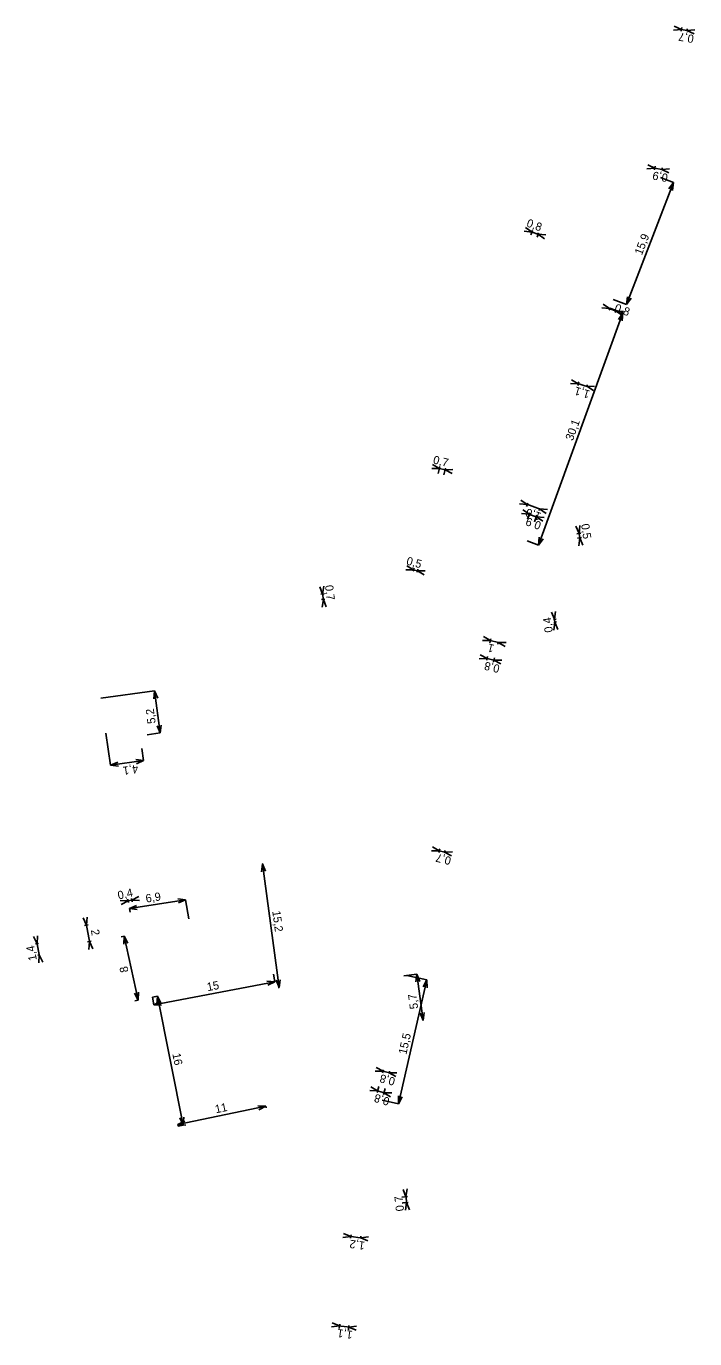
# Model space of a CAD drawing. Extents: x -732085 to -731961, y -1048713 to -1047966.
# Drawn here: x -732085.2 to -732003.6, y -1048336.6 to -1048176.6 of the extents above; entities that cross this region are included whole.
import ezdxf

# ---------------------------------------------------------------- set-up
doc = ezdxf.new("R2010")
doc.units = 0
doc.layers.add('Kota_NN', color=7, linetype='Continuous')
doc.layers.add('Kota_VN', color=7, linetype='Continuous')

msp = doc.modelspace()

# ---------------------------------------------------------------- linework, layer by layer
at = {"layer": 'Kota_NN'}
for p, q in [((-732011.96, -1048210.54), (-732006.25, -1048195.66)), ((-732007.84, -1048195.05), (-732006.25, -1048195.66)), ((-732006.25, -1048195.66), (-732006.81, -1048196.44)), ((-732006.25, -1048195.66), (-732006.35, -1048196.62)), ((-732023.5, -1048201.7), (-732024.46, -1048201.61)), ((-732023.5, -1048201.7), (-732024.29, -1048201.14)), ((-732023.69, -1048201.63), (-732022.58, -1048202.03)), ((-732023.63, -1048202.04), (-732023.44, -1048201.51)), ((-732022.89, -1048202.31), (-732022.7, -1048201.78)), ((-732022.77, -1048201.96), (-732021.81, -1048202.05)), ((-732022.77, -1048201.96), (-732021.98, -1048202.51)), ((-732013.59, -1048209.91), (-732011.96, -1048210.54)), ((-732011.96, -1048210.54), (-732011.86, -1048209.58)), ((-732011.96, -1048210.54), (-732011.4, -1048209.76)), ((-732022.7, -1048239.87), (-732012.41, -1048211.56)), ((-732014.03, -1048211.04), (-732014.98, -1048210.96)), ((-732014.03, -1048211.04), (-732014.82, -1048210.5)), ((-732014.21, -1048210.98), (-732013.11, -1048211.37)), ((-732014.01, -1048210.99), (-732014.09, -1048211.23)), ((-732014, -1048210.98), (-732012.41, -1048211.56)), ((-732013.28, -1048211.25), (-732013.37, -1048211.49)), ((-732013.3, -1048211.31), (-732012.34, -1048211.39)), ((-732013.3, -1048211.31), (-732012.51, -1048211.85)), ((-732012.41, -1048211.56), (-732012.96, -1048212.35)), ((-732012.41, -1048211.56), (-732012.5, -1048212.52)), ((-732034.78, -1048230.52), (-732035.74, -1048230.54)), ((-732034.78, -1048230.52), (-732035.63, -1048230.05)), ((-732034.98, -1048230.47), (-732033.91, -1048230.73)), ((-732034.93, -1048231.12), (-732034.74, -1048230.32)), ((-732034.25, -1048231.29), (-732034.06, -1048230.49)), ((-732034.1, -1048230.68), (-732033.14, -1048230.66)), ((-732034.1, -1048230.68), (-732033.26, -1048231.14)), ((-732023.82, -1048236.1), (-732024.61, -1048235.55)), ((-732024.04, -1048236.71), (-732023.76, -1048235.92)), ((-732023.82, -1048236.1), (-732024.78, -1048236.02)), ((-732022.78, -1048236.48), (-732024.01, -1048236.04)), ((-732023.19, -1048237.02), (-732022.9, -1048236.23)), ((-732022.97, -1048236.41), (-732022.01, -1048236.5)), ((-732022.97, -1048236.41), (-732022.18, -1048236.96)), ((-732017.76, -1048238.44), (-732018.14, -1048237.56)), ((-732017.76, -1048238.44), (-732017.65, -1048237.48)), ((-732022.7, -1048239.87), (-732022.61, -1048238.91)), ((-732022.7, -1048239.87), (-732022.15, -1048239.08)), ((-732018.03, -1048238.48), (-732017.56, -1048238.41)), ((-732017.95, -1048239.01), (-732017.48, -1048238.94)), ((-732017.79, -1048238.24), (-732017.64, -1048239.17)), ((-732017.67, -1048238.97), (-732017.78, -1048239.93)), ((-732017.67, -1048238.97), (-732017.29, -1048239.85)), ((-732024.09, -1048239.36), (-732022.7, -1048239.87)), ((-732037.94, -1048242.88), (-732038.78, -1048242.4)), ((-732037.94, -1048242.88), (-732038.9, -1048242.88)), ((-732038.14, -1048242.83), (-732037.29, -1048243.05)), ((-732037.98, -1048243.02), (-732037.89, -1048242.69)), ((-732037.52, -1048243.14), (-732037.43, -1048242.81)), ((-732037.48, -1048243), (-732036.52, -1048243)), ((-732037.48, -1048243), (-732036.65, -1048243.48)), ((-732049.04, -1048245.83), (-732049.4, -1048244.94)), ((-732049.04, -1048245.83), (-732048.9, -1048244.88)), ((-732049.24, -1048245.86), (-732048.84, -1048245.81)), ((-732049.16, -1048246.51), (-732048.76, -1048246.46)), ((-732048.95, -1048246.48), (-732049.09, -1048247.44)), ((-732049.06, -1048245.64), (-732048.93, -1048246.68)), ((-732048.95, -1048246.48), (-732048.59, -1048247.37)), ((-732020.76, -1048248.9), (-732021.14, -1048248.02)), ((-732020.69, -1048249.46), (-732020.79, -1048248.71)), ((-732020.76, -1048248.9), (-732020.64, -1048247.95)), ((-732020.88, -1048248.92), (-732020.57, -1048248.88)), ((-732020.83, -1048249.28), (-732020.52, -1048249.23)), ((-732020.71, -1048249.26), (-732020.83, -1048250.21)), ((-732020.71, -1048249.26), (-732020.34, -1048250.15)), ((-732028.98, -1048253.7), (-732029.82, -1048253.24)), ((-732028.91, -1048253.43), (-732029.02, -1048253.89)), ((-732028.98, -1048253.7), (-732029.94, -1048253.72)), ((-732027.96, -1048253.94), (-732029.17, -1048253.65)), ((-732028.09, -1048253.62), (-732028.2, -1048254.09)), ((-732028.15, -1048253.89), (-732027.19, -1048253.87)), ((-732028.15, -1048253.89), (-732027.31, -1048254.35)), ((-732076.09, -1048258.53), (-732069.53, -1048257.64)), ((-732069.53, -1048257.64), (-732069.65, -1048258.6)), ((-732068.84, -1048262.75), (-732069.53, -1048257.64)), ((-732069.53, -1048257.64), (-732069.16, -1048258.53)), ((-732075.47, -1048262.79), (-732074.92, -1048266.7)), ((-732070.45, -1048262.97), (-732068.84, -1048262.75)), ((-732068.84, -1048262.75), (-732069.21, -1048261.87)), ((-732068.84, -1048262.75), (-732068.72, -1048261.8)), ((-732071.08, -1048264.67), (-732070.88, -1048266.13)), ((-732070.88, -1048266.13), (-732074.92, -1048266.7)), ((-732074.92, -1048266.7), (-732074.03, -1048266.32)), ((-732070.88, -1048266.13), (-732071.83, -1048266.01)), ((-732070.88, -1048266.13), (-732071.76, -1048266.5)), ((-732074.92, -1048266.7), (-732073.96, -1048266.82)), ((-732072.77, -1048283.21), (-732073.73, -1048283.17)), ((-732072.77, -1048283.21), (-732073.62, -1048283.65)), ((-732072.96, -1048283.26), (-732072.14, -1048283.08)), ((-732072.72, -1048283.44), (-732072.81, -1048283.02)), ((-732072.6, -1048284.17), (-732065.76, -1048283.08)), ((-732072.6, -1048284.17), (-732071.73, -1048283.78)), ((-732072.28, -1048283.34), (-732072.37, -1048282.92)), ((-732072.33, -1048283.12), (-732071.48, -1048282.68)), ((-732072.33, -1048283.12), (-732071.37, -1048283.16)), ((-732065.76, -1048283.08), (-732066.72, -1048282.98)), ((-732065.76, -1048283.08), (-732066.64, -1048283.47)), ((-732065.38, -1048285.42), (-732065.76, -1048283.08)), ((-732077.83, -1048286.17), (-732078.24, -1048285.3)), ((-732077.83, -1048286.17), (-732077.75, -1048285.21)), ((-732072.53, -1048284.61), (-732072.6, -1048284.17)), ((-732072.6, -1048284.17), (-732071.65, -1048284.27)), ((-732078.09, -1048286.22), (-732077.64, -1048286.14)), ((-732077.87, -1048285.97), (-732077.44, -1048288.38)), ((-732077.73, -1048288.23), (-732077.28, -1048288.15)), ((-732077.47, -1048288.18), (-732077.55, -1048289.14)), ((-732077.47, -1048288.18), (-732077.07, -1048289.05)), ((-732073.63, -1048287.62), (-732073.23, -1048287.53)), ((-732073.23, -1048287.53), (-732073.28, -1048288.49)), ((-732071.55, -1048295.32), (-732073.23, -1048287.53)), ((-732073.23, -1048287.53), (-732072.79, -1048288.39)), ((-732069.64, -1048295.88), (-732054.87, -1048293.08)), ((-732054.87, -1048293.08), (-732055.83, -1048293.01)), ((-732054.87, -1048293.08), (-732055.74, -1048293.5)), ((-732055.05, -1048292.16), (-732054.87, -1048293.08)), ((-732039.77, -1048307.95), (-732036.34, -1048292.86)), ((-732038.77, -1048292.31), (-732036.34, -1048292.86)), ((-732036.34, -1048292.86), (-732036.79, -1048293.71)), ((-732036.34, -1048292.86), (-732036.31, -1048293.82)), ((-732071.55, -1048295.32), (-732071.99, -1048294.46)), ((-732071.55, -1048295.32), (-732071.5, -1048294.36)), ((-732069.81, -1048294.96), (-732069.2, -1048294.84)), ((-732069.81, -1048294.96), (-732069.64, -1048295.88)), ((-732069.2, -1048294.84), (-732069.26, -1048295.8)), ((-732069.2, -1048294.84), (-732066.05, -1048310.55)), ((-732069.2, -1048294.84), (-732068.77, -1048295.7)), ((-732071.95, -1048295.4), (-732071.55, -1048295.32)), ((-732069.64, -1048295.88), (-732068.77, -1048295.47)), ((-732069.64, -1048295.88), (-732068.68, -1048295.95)), ((-732042.33, -1048306.38), (-732043.29, -1048306.35)), ((-732042.33, -1048306.38), (-732043.15, -1048305.88)), ((-732041.37, -1048306.67), (-732042.52, -1048306.32)), ((-732042.17, -1048305.85), (-732042.39, -1048306.57)), ((-732041.4, -1048306.08), (-732041.62, -1048306.81)), ((-732041.76, -1048307.5), (-732039.77, -1048307.95)), ((-732041.56, -1048306.61), (-732040.6, -1048306.64)), ((-732041.56, -1048306.61), (-732040.75, -1048307.12)), ((-732039.77, -1048307.95), (-732039.8, -1048306.99)), ((-732039.77, -1048307.95), (-732039.32, -1048307.1)), ((-732066.69, -1048310.49), (-732055.97, -1048308.26)), ((-732066.05, -1048310.55), (-732065.98, -1048309.59)), ((-732055.97, -1048308.26), (-732056.93, -1048308.21)), ((-732055.97, -1048308.26), (-732056.83, -1048308.7)), ((-732055.93, -1048308.45), (-732055.97, -1048308.26)), ((-732066.69, -1048310.49), (-732065.83, -1048310.06)), ((-732066.66, -1048310.67), (-732066.69, -1048310.49)), ((-732066.69, -1048310.49), (-732065.73, -1048310.55)), ((-732066.66, -1048310.67), (-732066.05, -1048310.55)), ((-732066.05, -1048310.55), (-732066.47, -1048309.68)), ((-732038.88, -1048319.29), (-732039.23, -1048318.4)), ((-732038.78, -1048320.19), (-732038.9, -1048319.09)), ((-732038.88, -1048319.29), (-732038.73, -1048318.34)), ((-732039.36, -1048319.35), (-732038.68, -1048319.27)), ((-732039.29, -1048320.04), (-732038.61, -1048319.97)), ((-732038.8, -1048319.99), (-732038.95, -1048320.94)), ((-732038.8, -1048319.99), (-732038.46, -1048320.89)), ((-732046.99, -1048335.02), (-732047.94, -1048335.15)), ((-732046.99, -1048335.02), (-732047.87, -1048334.65)), ((-732045.65, -1048335.2), (-732047.19, -1048335)), ((-732047.03, -1048335.35), (-732046.96, -1048334.83)), ((-732045.9, -1048335.5), (-732045.83, -1048334.98)), ((-732045.85, -1048335.18), (-732044.9, -1048335.05)), ((-732045.85, -1048335.18), (-732044.97, -1048335.55))]:
    msp.add_line(p, q, dxfattribs=at)
at = {"layer": 'Kota_VN'}
for p, q in [((-732005.28, -1048177.02), (-732006.15, -1048176.62)), ((-732005.23, -1048176.76), (-732005.31, -1048177.22)), ((-732005.28, -1048177.02), (-732006.23, -1048177.11)), ((-732004.41, -1048177.18), (-732005.47, -1048176.99)), ((-732004.61, -1048177.15), (-732004.57, -1048176.94)), ((-732004.6, -1048177.14), (-732003.65, -1048177.06)), ((-732004.6, -1048177.14), (-732003.73, -1048177.55)), ((-732008.52, -1048193.93), (-732009.48, -1048194)), ((-732008.52, -1048193.93), (-732009.39, -1048193.51)), ((-732007.47, -1048194.12), (-732008.72, -1048193.89)), ((-732008.48, -1048193.68), (-732008.56, -1048194.12)), ((-732007.67, -1048194.1), (-732007.63, -1048193.89)), ((-732007.67, -1048194.09), (-732006.71, -1048194.01)), ((-732007.67, -1048194.09), (-732006.8, -1048194.5)), ((-732017.86, -1048220.2), (-732018.69, -1048219.7)), ((-732017.8, -1048219.96), (-732017.92, -1048220.39)), ((-732017.86, -1048220.2), (-732018.82, -1048220.18)), ((-732016.64, -1048220.56), (-732018.06, -1048220.14)), ((-732016.83, -1048220.51), (-732016.78, -1048220.31)), ((-732016.83, -1048220.5), (-732015.87, -1048220.52)), ((-732016.83, -1048220.5), (-732016.01, -1048221)), ((-732024.08, -1048234.92), (-732024.87, -1048234.37)), ((-732024.08, -1048234.92), (-732025.03, -1048234.84)), ((-732022.38, -1048235.52), (-732024.27, -1048234.85)), ((-732024.16, -1048235.14), (-732024.01, -1048234.73)), ((-732022.57, -1048235.44), (-732022.64, -1048235.64)), ((-732022.57, -1048235.45), (-732021.61, -1048235.53)), ((-732022.57, -1048235.45), (-732021.78, -1048236)), ((-732028.58, -1048251.48), (-732029.55, -1048251.49)), ((-732028.58, -1048251.48), (-732029.42, -1048251.01)), ((-732027.43, -1048251.79), (-732028.78, -1048251.43)), ((-732028.66, -1048251.78), (-732028.54, -1048251.29)), ((-732027.62, -1048251.73), (-732027.67, -1048251.93)), ((-732027.62, -1048251.74), (-732026.66, -1048251.73)), ((-732027.62, -1048251.74), (-732026.79, -1048252.21)), ((-732034.81, -1048277.12), (-732035.77, -1048277.14)), ((-732034.81, -1048277.12), (-732035.65, -1048276.65)), ((-732033.96, -1048277.32), (-732035, -1048277.07)), ((-732034.76, -1048276.9), (-732034.86, -1048277.31)), ((-732034.16, -1048277.29), (-732034.11, -1048277.08)), ((-732034.16, -1048277.28), (-732033.19, -1048277.25)), ((-732034.16, -1048277.28), (-732033.31, -1048277.74)), ((-732056.36, -1048278.72), (-732056.49, -1048279.68)), ((-732056.35, -1048278.72), (-732056.36, -1048278.72)), ((-732056.36, -1048278.72), (-732054.35, -1048293.79)), ((-732056.36, -1048278.72), (-732056, -1048279.61)), ((-732083.87, -1048288.44), (-732084.29, -1048287.58)), ((-732084.05, -1048288.47), (-732083.68, -1048288.4)), ((-732083.56, -1048290.01), (-732083.91, -1048288.24)), ((-732083.87, -1048288.44), (-732083.81, -1048287.48)), ((-732083.59, -1048289.81), (-732083.8, -1048289.85)), ((-732083.6, -1048289.82), (-732083.66, -1048290.77)), ((-732083.6, -1048289.82), (-732083.18, -1048290.68)), ((-732054.35, -1048293.79), (-732054.72, -1048292.9)), ((-732054.35, -1048293.79), (-732054.23, -1048292.83)), ((-732039.13, -1048292.37), (-732037.55, -1048292.16)), ((-732037.55, -1048292.16), (-732037.67, -1048293.11)), ((-732036.79, -1048297.8), (-732037.55, -1048292.16)), ((-732037.55, -1048292.16), (-732037.18, -1048293.04)), ((-732054.47, -1048293.8), (-732054.35, -1048293.79)), ((-732036.79, -1048297.8), (-732037.16, -1048296.91)), ((-732036.79, -1048297.8), (-732036.66, -1048296.84)), ((-732036.78, -1048297.8), (-732036.79, -1048297.8)), ((-732041.67, -1048303.99), (-732042.63, -1048304)), ((-732041.67, -1048303.99), (-732042.51, -1048303.52)), ((-732040.74, -1048304.23), (-732041.87, -1048303.94)), ((-732041.63, -1048303.81), (-732041.72, -1048304.18)), ((-732040.94, -1048304.19), (-732040.88, -1048303.99)), ((-732040.93, -1048304.18), (-732039.97, -1048304.17)), ((-732040.93, -1048304.18), (-732040.1, -1048304.65)), ((-732045.6, -1048324.13), (-732046.49, -1048323.75)), ((-732045.58, -1048323.94), (-732045.63, -1048324.33)), ((-732045.6, -1048324.13), (-732046.56, -1048324.24)), ((-732044.2, -1048324.33), (-732045.8, -1048324.1)), ((-732044.4, -1048324.31), (-732044.37, -1048324.1)), ((-732044.4, -1048324.3), (-732043.45, -1048324.19)), ((-732044.4, -1048324.3), (-732043.52, -1048324.68))]:
    msp.add_line(p, q, dxfattribs=at)

# ---------------------------------------------------------------- texts
at = {"layer": 'Kota_NN'}
for s, rotation, p in [('0,8', 339.9552, (-732024.25, -1048201)), ('15,9', 68.9675, (-732010.1, -1048204.58)), ('0,8', 340.1762, (-732013.53, -1048211.34)), ('30,1', 70.0285, (-732018.53, -1048227.21)), ('0,7', 346.3718, (-732035.64, -1048229.9)), ('0,9', 160.0394, (-732022.29, -1048237.09)), ('0,5', 278.6635, (-732017.52, -1048237.33)), ('0,5', 345.2694, (-732038.9, -1048242.22)), ('0,7', 277.1501, (-732048.76, -1048244.79)), ('0,4', 97.8801, (-732020.95, -1048250.45)), ('0,8', 166.6168, (-732027.37, -1048254.49)), ('5,2', 97.6941, (-732069.4, -1048261.57)), ('4,1', 188.1082, (-732071.61, -1048266.63)), ('0,4', 12.2768, (-732073.93, -1048283.06)), ('6,9', 9.0945, (-732070.55, -1048283.44)), ('2', 280.1532, (-732077.32, -1048286.78)), ('8', 102.1896, (-732072.71, -1048291.84)), ('15', 10.7502, (-732063.06, -1048294.23)), ('15,5', 77.2275, (-732038.83, -1048302.01)), ('16', 281.3527, (-732067.38, -1048301.88)), ('11', 11.7255, (-732062.06, -1048309.12)), ('0,8', 163.196, (-732040.79, -1048307.26)), ('0,7', 96.1834, (-732039.1, -1048321)), ('1,1', 172.4036, (-732045.33, -1048335.65))]:
    msp.add_text(s, height=1, rotation=rotation, dxfattribs=at).set_placement(p)
at = {"layer": 'Kota_VN'}
for s, rotation, p in [('0,7', 170.1075, (-732003.7, -1048177.7)), ('0,9', 169.4722, (-732006.86, -1048194.64)), ('1,1', 163.7299, (-732016.35, -1048221.06)), ('1,6', 160.4216, (-732022.29, -1048235.98)), ('1', 165.2691, (-732028.04, -1048252.04)), ('0,7', 166.296, (-732033.29, -1048277.9)), ('15,2', 277.6194, (-732055.19, -1048284.48)), ('1,4', 101.1633, (-732083.89, -1048290.42)), ('5,7', 97.7428, (-732037.39, -1048296.35)), ('0,8', 165.6619, (-732040.12, -1048304.8)), ('1,2', 171.8875, (-732043.83, -1048324.79))]:
    msp.add_text(s, height=1, rotation=rotation, dxfattribs=at).set_placement(p)

doc.saveas('drawing.dxf')
